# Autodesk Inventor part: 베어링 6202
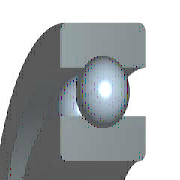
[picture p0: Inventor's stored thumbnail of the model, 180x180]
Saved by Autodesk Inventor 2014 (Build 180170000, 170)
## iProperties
IsCustomPart: 1
Created: 2015-12
Part Number: 베어링 6202
Material: 강철, 연강
Description: 깊은 그루브 볼 베어링
Document SubType Name: Modeling
Standard: KS B 2023
Designer: mdu
Standards Organization: KS
Language: ko-KR
Size Designation: 6202 - 15 x 35 x 11
Categories: <MemberInstance><Categories><Category DisplayName="샤프트 부품" InternalName="7f7aeb1f-a693-4053-b835-cee3144e0d98" Mnemonic="SHFT"><Category DisplayName="베어링" Inter
Density: 7.86 g/cm^3
Mass: 42.4004 g
Surface Area: 51.5584 cm^2
Volume: 5.39445 cm^3
Appearance: 노란색
Author: mdu
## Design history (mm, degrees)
sketch "스케치" dims "d0" = 5.2 (= -0.26 x WD + 0.26 x BD)
  geometry: L1 (2.9, 12.5)-(8.1, 12.5); L2 (5.5, 12.5)-(5.5, 9.9); L3 (5.5, 12.5)-(5.5, 15.1); L4 (3.568, 10.76)-(0, 10.76); L5 (0, 7.5)-(11, 7.5); L6 (3.568, 14.24)-(0, 14.24); L7 (0, 17.5)-(11, 17.5); L8 (11, 7.5)-(11, 10.76); L9 (7.432, 10.76)-(11, 10.76); L10 (7.432, 14.24)-(11, 14.24); L11 (11, 17.5)-(11, 14.24); L12 (-1.4, 0)-(8.4, 0) reference; L13 (0, -0.3)-(0, 5.3) reference
  constraints: 22 end point, 4 point on line, 2 collinear, 2 perpendicular, 2 symmetric about line, 1 midpoint, 1 parallel, 14 other
  dimensions: "d9" = 15 diameter of L5 L12 (= WD); "d11" = 35 diameter of L7 L12 (= BD); "d12" = 11 distance between parallel lines of L8 L13 (= KB); "d13" = 21.52 diameter of L9 L12 (= 0.326 x BD + 0.674 x WD)
revolve "본체" stored, may be unused: angle "d6" = 90 deg
revolve "볼" stored, may be unused: angle "d7" = 90 deg
pattern_circular "IDS_ARRAYBALL[SIMPL:T]" dims angle "d3" = 360 deg
body "Solid1"
fillet "모깎기1" dims "d1" = 0.6 (= KRS)
other parameters: "WD" = 15 [user parameter; used in 5 equation terms], "BD" = 35 [user parameter; used in 5 equation terms], "KB" = 11 [user parameter; used in 1 equation term], "KRS" = 0.6 [user parameter; used in 1 equation term], "d4" = 0, "d5" = 0, "d8" = 0, "d14" = 0, "d15" = 0, "BBA" = 0 [user parameter], "BC0" = 3750000 [user parameter], "BC" = 7800000 [user parameter], "BR" = 17.5 (= 0.5 x BD) [user parameter], "WR" = 7.5 (= 0.5 x WD) [user parameter]
